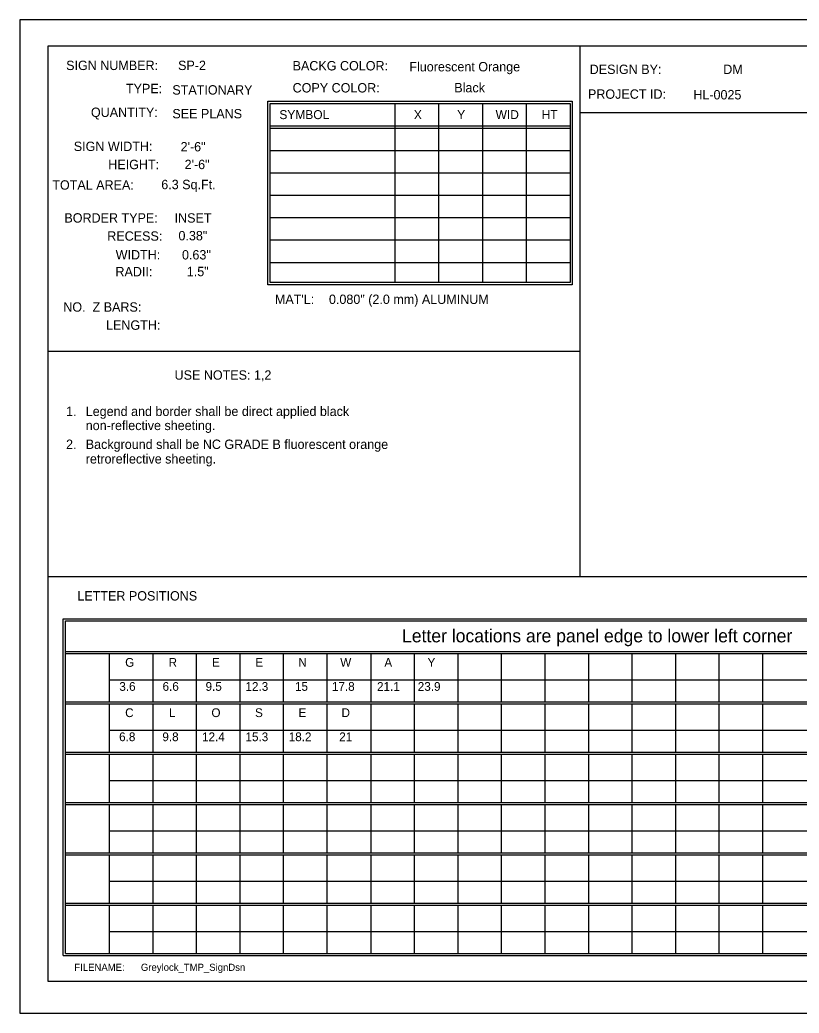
# Model space of a CAD drawing. Extents: x 1788.1 to 1851.2, y 237.2 to 283.4.
# Drawn here: x 1821.02 to 1837.39, y 262.55 to 283.41 of the extents above; entities that cross this region are included whole.
import ezdxf

# ---------------------------------------------------------------- set-up
doc = ezdxf.new("R2010")
doc.units = 0
for name, color, linetype in [('Old_Level_2', 7, 'Continuous'), ('Old_Level_3', 7, 'Continuous'), ('Old_Level_7', 7, 'Continuous'), ('Sheet Plot Border Outside CELL', 7, 'Continuous')]:
    doc.layers.add(name, color=color, linetype=linetype)

msp = doc.modelspace()

# ---------------------------------------------------------------- linework, layer by layer
at = {"layer": 'Old_Level_2'}
for p, q in [((1832.78, 282.859), (1832.78, 271.718)), ((1828.894, 281.65), (1828.894, 277.892)), ((1829.814, 281.65), (1829.814, 277.892)), ((1830.734, 281.65), (1830.734, 277.892)), ((1831.654, 281.65), (1831.654, 277.892)), ((1832.78, 281.461), (1849.944, 281.461)), ((1826.278, 281.181), (1832.575, 281.181)), ((1826.278, 281.134), (1832.575, 281.134)), ((1826.278, 280.664), (1832.575, 280.664)), ((1826.278, 280.194), (1832.575, 280.194)), ((1826.278, 279.725), (1832.575, 279.725)), ((1826.278, 279.255), (1832.575, 279.255)), ((1826.278, 278.785), (1832.575, 278.785)), ((1826.278, 278.315), (1832.575, 278.315)), ((1832.78, 276.442), (1821.618, 276.442)), ((1821.618, 271.718), (1832.78, 271.718)), ((1832.78, 271.718), (1849.944, 271.718)), ((1821.981, 270.146), (1843.759, 270.146)), ((1821.981, 270.1), (1843.759, 270.1)), ((1822.9, 270.1), (1822.9, 269.089)), ((1823.818, 270.1), (1823.818, 269.089)), ((1824.727, 270.1), (1824.727, 269.089)), ((1825.645, 270.1), (1825.645, 269.089)), ((1826.554, 270.1), (1826.554, 269.089)), ((1827.472, 270.1), (1827.472, 269.089)), ((1828.39, 270.1), (1828.39, 269.089)), ((1829.299, 270.1), (1829.299, 269.089)), ((1830.218, 270.1), (1830.218, 269.089)), ((1831.126, 270.1), (1831.126, 269.089)), ((1832.045, 270.1), (1832.045, 269.089)), ((1832.963, 270.1), (1832.963, 269.089)), ((1833.872, 270.1), (1833.872, 269.089)), ((1834.79, 270.1), (1834.79, 269.089)), ((1835.699, 270.1), (1835.699, 269.089)), ((1836.617, 270.1), (1836.617, 269.089)), ((1822.9, 269.548), (1843.759, 269.548)), ((1821.981, 269.089), (1843.759, 269.089)), ((1821.981, 269.043), (1843.759, 269.043)), ((1822.9, 269.043), (1822.9, 268.033)), ((1823.818, 269.043), (1823.818, 268.033)), ((1824.727, 269.043), (1824.727, 268.033)), ((1825.645, 269.043), (1825.645, 268.033)), ((1826.554, 269.043), (1826.554, 268.033)), ((1827.472, 269.043), (1827.472, 268.033)), ((1828.39, 269.043), (1828.39, 268.033)), ((1829.299, 269.043), (1829.299, 268.033)), ((1830.218, 269.043), (1830.218, 268.033)), ((1831.126, 269.043), (1831.126, 268.033)), ((1832.045, 269.043), (1832.045, 268.033)), ((1832.963, 269.043), (1832.963, 268.033)), ((1833.872, 269.043), (1833.872, 268.033)), ((1834.79, 269.043), (1834.79, 268.033)), ((1835.699, 269.043), (1835.699, 268.033)), ((1836.617, 269.043), (1836.617, 268.033)), ((1822.9, 268.492), (1843.759, 268.492)), ((1821.981, 268.033), (1843.759, 268.033)), ((1821.981, 267.987), (1843.759, 267.987)), ((1822.9, 267.987), (1822.9, 266.976)), ((1823.818, 267.987), (1823.818, 266.976)), ((1824.727, 267.987), (1824.727, 266.976)), ((1825.645, 267.987), (1825.645, 266.976)), ((1826.554, 267.987), (1826.554, 266.976)), ((1827.472, 267.987), (1827.472, 266.976)), ((1828.39, 267.987), (1828.39, 266.976)), ((1829.299, 267.987), (1829.299, 266.976)), ((1830.218, 267.987), (1830.218, 266.976)), ((1831.126, 267.987), (1831.126, 266.976)), ((1832.045, 267.987), (1832.045, 266.976)), ((1832.963, 267.987), (1832.963, 266.976)), ((1833.872, 267.987), (1833.872, 266.976)), ((1834.79, 267.987), (1834.79, 266.976)), ((1835.699, 267.987), (1835.699, 266.976)), ((1836.617, 267.987), (1836.617, 266.976)), ((1822.9, 267.436), (1843.759, 267.436)), ((1821.981, 266.976), (1843.759, 266.976)), ((1821.981, 266.93), (1843.759, 266.93)), ((1822.9, 266.93), (1822.9, 265.92)), ((1823.818, 266.93), (1823.818, 265.92)), ((1824.727, 266.93), (1824.727, 265.92)), ((1825.645, 266.93), (1825.645, 265.92)), ((1826.554, 266.93), (1826.554, 265.92)), ((1827.472, 266.93), (1827.472, 265.92)), ((1828.39, 266.93), (1828.39, 265.92)), ((1829.299, 266.93), (1829.299, 265.92)), ((1830.218, 266.93), (1830.218, 265.92)), ((1831.126, 266.93), (1831.126, 265.92)), ((1832.045, 266.93), (1832.045, 265.92)), ((1832.963, 266.93), (1832.963, 265.92)), ((1833.872, 266.93), (1833.872, 265.92)), ((1834.79, 266.93), (1834.79, 265.92)), ((1835.699, 266.93), (1835.699, 265.92)), ((1836.617, 266.93), (1836.617, 265.92)), ((1822.9, 266.379), (1843.759, 266.379)), ((1821.981, 265.92), (1843.759, 265.92)), ((1821.981, 265.92), (1843.759, 265.92)), ((1822.9, 266.037), (1822.9, 265.92)), ((1823.818, 266.037), (1823.818, 265.92)), ((1824.727, 266.037), (1824.727, 265.92)), ((1825.645, 266.037), (1825.645, 265.92)), ((1826.554, 266.037), (1826.554, 265.92)), ((1827.472, 266.037), (1827.472, 265.92)), ((1828.39, 266.037), (1828.39, 265.92)), ((1829.299, 266.037), (1829.299, 265.92)), ((1830.218, 266.037), (1830.218, 265.92)), ((1831.126, 266.037), (1831.126, 265.92)), ((1832.045, 266.037), (1832.045, 265.92)), ((1832.963, 266.037), (1832.963, 265.92)), ((1833.872, 266.037), (1833.872, 265.92)), ((1834.79, 266.037), (1834.79, 265.92)), ((1835.699, 266.037), (1835.699, 265.92)), ((1836.617, 266.037), (1836.617, 265.92)), ((1821.981, 265.874), (1843.759, 265.874)), ((1821.981, 265.874), (1843.759, 265.874)), ((1822.9, 265.874), (1822.9, 264.929)), ((1822.9, 265.874), (1822.9, 264.863)), ((1823.818, 265.874), (1823.818, 264.929)), ((1823.818, 265.874), (1823.818, 264.863)), ((1824.727, 265.874), (1824.727, 264.929)), ((1824.727, 265.874), (1824.727, 264.863)), ((1825.645, 265.874), (1825.645, 264.929)), ((1825.645, 265.874), (1825.645, 264.863)), ((1826.554, 265.874), (1826.554, 264.929)), ((1826.554, 265.874), (1826.554, 264.863)), ((1827.472, 265.874), (1827.472, 264.929)), ((1827.472, 265.874), (1827.472, 264.863)), ((1828.39, 265.874), (1828.39, 264.929)), ((1828.39, 265.874), (1828.39, 264.863)), ((1829.299, 265.874), (1829.299, 264.929)), ((1829.299, 265.874), (1829.299, 264.863)), ((1830.218, 265.874), (1830.218, 264.929)), ((1830.218, 265.874), (1830.218, 264.863)), ((1831.126, 265.874), (1831.126, 264.929)), ((1831.126, 265.874), (1831.126, 264.863)), ((1832.045, 265.874), (1832.045, 264.929)), ((1832.045, 265.874), (1832.045, 264.863)), ((1832.963, 265.874), (1832.963, 264.929)), ((1832.963, 265.874), (1832.963, 264.863)), ((1833.872, 265.874), (1833.872, 264.929)), ((1833.872, 265.874), (1833.872, 264.863)), ((1834.79, 265.874), (1834.79, 264.929)), ((1834.79, 265.874), (1834.79, 264.863)), ((1835.699, 265.874), (1835.699, 264.929)), ((1835.699, 265.874), (1835.699, 264.863)), ((1836.617, 265.874), (1836.617, 264.929)), ((1836.617, 265.874), (1836.617, 264.863)), ((1822.9, 265.323), (1843.759, 265.323)), ((1822.9, 265.323), (1843.759, 265.323)), ((1821.981, 264.863), (1843.759, 264.863)), ((1821.981, 264.863), (1843.759, 264.863)), ((1822.9, 264.981), (1822.9, 264.863)), ((1823.818, 264.981), (1823.818, 264.863)), ((1824.727, 264.981), (1824.727, 264.863)), ((1825.645, 264.981), (1825.645, 264.863)), ((1826.554, 264.981), (1826.554, 264.863)), ((1827.472, 264.981), (1827.472, 264.863)), ((1828.39, 264.981), (1828.39, 264.863)), ((1829.299, 264.981), (1829.299, 264.863)), ((1830.218, 264.981), (1830.218, 264.863)), ((1831.126, 264.981), (1831.126, 264.863)), ((1832.045, 264.981), (1832.045, 264.863)), ((1832.963, 264.981), (1832.963, 264.863)), ((1833.872, 264.981), (1833.872, 264.863)), ((1834.79, 264.981), (1834.79, 264.863)), ((1835.699, 264.981), (1835.699, 264.863)), ((1836.617, 264.981), (1836.617, 264.863)), ((1821.981, 264.817), (1843.759, 264.817)), ((1821.981, 264.817), (1843.759, 264.817)), ((1822.9, 264.817), (1822.9, 263.807)), ((1822.9, 264.817), (1822.9, 263.807)), ((1823.818, 264.817), (1823.818, 263.807)), ((1823.818, 264.817), (1823.818, 263.807)), ((1824.727, 264.817), (1824.727, 263.807)), ((1824.727, 264.817), (1824.727, 263.807)), ((1825.645, 264.817), (1825.645, 263.807)), ((1825.645, 264.817), (1825.645, 263.807)), ((1826.554, 264.817), (1826.554, 263.807)), ((1826.554, 264.817), (1826.554, 263.807)), ((1827.472, 264.817), (1827.472, 263.807)), ((1827.472, 264.817), (1827.472, 263.807)), ((1828.39, 264.817), (1828.39, 263.807)), ((1828.39, 264.817), (1828.39, 263.807)), ((1829.299, 264.817), (1829.299, 263.807)), ((1829.299, 264.817), (1829.299, 263.807)), ((1830.218, 264.817), (1830.218, 263.807)), ((1830.218, 264.817), (1830.218, 263.807)), ((1831.126, 264.817), (1831.126, 263.807)), ((1831.126, 264.817), (1831.126, 263.807)), ((1832.045, 264.817), (1832.045, 263.807)), ((1832.045, 264.817), (1832.045, 263.807)), ((1832.963, 264.817), (1832.963, 263.807)), ((1832.963, 264.817), (1832.963, 263.807)), ((1833.872, 264.817), (1833.872, 263.807)), ((1833.872, 264.817), (1833.872, 263.807)), ((1834.79, 264.817), (1834.79, 263.807)), ((1834.79, 264.817), (1834.79, 263.807)), ((1835.699, 264.817), (1835.699, 263.807)), ((1835.699, 264.817), (1835.699, 263.807)), ((1836.617, 264.817), (1836.617, 263.807)), ((1836.617, 264.817), (1836.617, 263.807)), ((1822.9, 264.266), (1843.759, 264.266)), ((1822.9, 264.266), (1843.759, 264.266)), ((1821.981, 263.807), (1843.759, 263.807)), ((1821.981, 263.807), (1843.759, 263.807)), ((1821.934, 263.761), (1843.759, 263.761)), ((1821.981, 263.761), (1843.759, 263.761))]:
    msp.add_line(p, q, dxfattribs=at)
for points in [[(1821.618, 282.859), (1849.944, 282.859), (1849.944, 263.214), (1821.618, 263.214)], [(1826.23, 281.698), (1832.623, 281.698), (1832.623, 277.845), (1826.23, 277.845)], [(1826.278, 281.65), (1832.575, 281.65), (1832.575, 277.892), (1826.278, 277.892)]]:
    msp.add_lwpolyline(points, close=True, dxfattribs=at)
for points in [[(1821.934, 264.929), (1821.934, 270.834), (1843.759, 270.834)], [(1821.981, 264.929), (1821.981, 270.789), (1843.759, 270.789)], [(1821.934, 263.761), (1821.934, 266.037)], [(1821.981, 263.807), (1821.981, 266.037)]]:
    msp.add_lwpolyline(points, dxfattribs=at)
at = {"layer": 'Sheet Plot Border Outside CELL'}
msp.add_lwpolyline([(1851.194, 283.406), (1821.023, 283.406), (1821.023, 262.552), (1851.194, 262.552)], close=True, dxfattribs=at)

# ---------------------------------------------------------------- texts
at = {"layer": 'Old_Level_2'}
for s, height, p in [('SIGN NUMBER:', 0.19685, (1821.995, 282.352)), ('BACKG COLOR:', 0.19685, (1826.75, 282.344)), ('DESIGN BY:', 0.1969, (1832.988, 282.269)), ('TYPE:', 0.1969, (1823.25, 281.866)), ('COPY COLOR:', 0.19685, (1826.75, 281.881)), ('PROJECT ID:', 0.19685, (1832.952, 281.749)), ('HL-0025', 0.1969, (1835.164, 281.735)), ('QUANTITY:', 0.1969, (1822.515, 281.367)), ('SIGN WIDTH:', 0.19685, (1822.155, 280.652)), ('HEIGHT:', 0.1969, (1822.879, 280.271)), ('TOTAL AREA:', 0.19685, (1821.704, 279.841)), ('BORDER TYPE:', 0.19685, (1821.958, 279.149)), ('RECESS:', 0.1969, (1822.858, 278.769)), ('WIDTH:', 0.1969, (1823.035, 278.375)), ('RADII:', 0.1969, (1823.03, 278.021)), ("MAT'L:", 0.1969, (1826.378, 277.441)), ('NO.  Z BARS:', 0.19685, (1821.935, 277.279)), ('LENGTH:', 0.1969, (1822.832, 276.899)), ('USE NOTES: 1,2', 0.19685, (1824.271, 275.851)), ('1.', 0.1969, (1821.993, 275.089)), ('Legend and border shall be direct applied black      ', 0.19685, (1822.406, 275.089)), ('2.', 0.1969, (1821.993, 274.397)), ('LETTER POSITIONS', 0.19685, (1822.23, 271.215)), ('Letter locations are panel edge to lower left corner', 0.27559, (1829.048, 270.337))]:
    msp.add_text(s, height=height, rotation=360, dxfattribs=at).set_placement(p)
for s, height, p in [('DM', 0.1969, (1835.793, 282.269)), ('SYMBOL', 0.1879, (1826.472, 281.322)), ('X', 0.188, (1829.296, 281.322)), ('Y', 0.188, (1830.206, 281.322)), ('WID', 0.1879, (1831.013, 281.322)), ('HT', 0.1879, (1831.979, 281.322)), ('0.080" (2.0 mm) ALUMINUM', 0.19685, (1827.513, 277.441)), ('non-reflective sheeting.', 0.19685, (1822.406, 274.793)), ('Background shall be NC GRADE B fluorescent orange', 0.19685, (1822.406, 274.397)), ('retroreflective sheeting.', 0.19685, (1822.406, 274.091)), ('G', 0.184, (1823.234, 269.824)), ('R', 0.184, (1824.146, 269.824)), ('E', 0.184, (1825.058, 269.824)), ('E', 0.184, (1825.966, 269.824)), ('N', 0.184, (1826.869, 269.824)), ('W', 0.184, (1827.75, 269.824)), ('A', 0.184, (1828.676, 269.824)), ('Y', 0.184, (1829.583, 269.824)), ('3.6', 0.1837, (1823.111, 269.319)), ('6.6', 0.1837, (1824.019, 269.319)), ('9.5', 0.1837, (1824.922, 269.319)), ('12.3', 0.1837, (1825.76, 269.319)), ('15', 0.1837, (1826.799, 269.319)), ('17.8', 0.1837, (1827.575, 269.319)), ('21.1', 0.1837, (1828.523, 269.319)), ('23.9', 0.1837, (1829.378, 269.319)), ('C', 0.184, (1823.234, 268.768)), ('L', 0.184, (1824.155, 268.768)), ('O', 0.184, (1825.045, 268.768)), ('S', 0.184, (1825.961, 268.768)), ('E', 0.184, (1826.873, 268.768)), ('D', 0.184, (1827.777, 268.768)), ('6.8', 0.1837, (1823.107, 268.262)), ('9.8', 0.1837, (1824.015, 268.262)), ('12.4', 0.1837, (1824.848, 268.262)), ('15.3', 0.1837, (1825.76, 268.262)), ('18.2', 0.1837, (1826.668, 268.262)), ('21', 0.1837, (1827.729, 268.262))]:
    msp.add_text(s, height=height, dxfattribs=at).set_placement(p)
at = {"layer": 'Old_Level_3'}
for s, p in [('SP-2', (1824.345, 282.352)), ('Black', (1830.145, 281.884))]:
    msp.add_text(s, height=0.1969, dxfattribs=at).set_placement(p)
for s, height, p in [('Fluorescent Orange', 0.19685, (1829.201, 282.324)), ('STATIONARY', 0.1969, (1824.225, 281.837)), ('SEE PLANS', 0.1969, (1824.225, 281.338)), ('2\'-6"', 0.1969, (1824.398, 280.644)), ('2\'-6"', 0.1969, (1824.482, 280.272)), ('6.3 Sq.Ft.', 0.1969, (1823.992, 279.851)), ('INSET', 0.1969, (1824.272, 279.148)), ('0.38"', 0.1969, (1824.353, 278.777)), ('0.63"', 0.1969, (1824.427, 278.375)), ('1.5"', 0.1969, (1824.528, 278.024))]:
    msp.add_text(s, height=height, rotation=360, dxfattribs=at).set_placement(p)
at = {"layer": 'Old_Level_7'}
for s, height, p in [('FILENAME:', 0.1497, (1822.167, 263.44)), ('Greylock_TMP_SignDsn', 0.14974, (1823.564, 263.44))]:
    msp.add_text(s, height=height, rotation=360, dxfattribs=at).set_placement(p)

doc.saveas('drawing.dxf')
